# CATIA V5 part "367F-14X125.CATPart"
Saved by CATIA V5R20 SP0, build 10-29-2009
Part number: 367F-14X125
Definition: NONE
Nomenclature: 367F-14X125
Source: Unknown
Description: 367F-14X125
Bounding box of the stored display mesh (mm): x 0 to 125, y -14 to 14, z -14 to 14
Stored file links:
  C:\Users\Utente\Desktop\IO LAVORO\3D X SITO CF\X SITO\PLASTICA\3D files 367\367F-14X125.CATPart
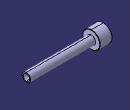
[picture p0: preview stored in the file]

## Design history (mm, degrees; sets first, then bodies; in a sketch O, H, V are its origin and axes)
Body1 "367F-14X125" (main body)
  Solid1: solid without history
